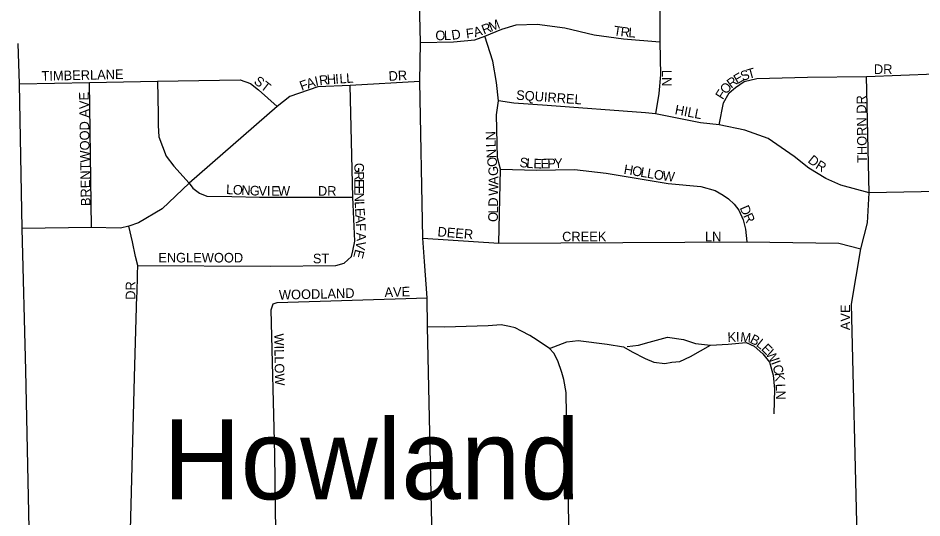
# Model space of a CAD drawing. Extents: x -37878.7 to -37844.7, y -19791.4 to -19769.4.
# Drawn here: x -37871.912 to -37871.021, y -19771.451 to -19770.958 of the extents above; entities that cross this region are included whole.
import ezdxf

# ---------------------------------------------------------------- set-up
doc = ezdxf.new("R2010")
doc.units = 0
for name, color, linetype in [('GM_X_State_Route', 7, 'Continuous'), ('GM_X_Township_Subdivision', 7, 'Continuous'), ('GM_X_Township_Subdivision_Text', 7, 'Continuous'), ('GM_X_Unincorporated_Text', 7, 'Continuous')]:
    doc.layers.add(name, color=color, linetype=linetype)

msp = doc.modelspace()

# ---------------------------------------------------------------- linework, layer by layer
at = {"layer": 'GM_X_State_Route'}
for points in [[(-37871.51143, -19771.19794), (-37871.51308, -19771.17482), (-37871.51633, -19771.02024), (-37871.51551, -19770.982), (-37871.51877, -19770.84776), (-37871.52447, -19770.72084), (-37871.52739, -19770.64449), (-37871.53594, -19770.42871), (-37871.53733, -19770.3854)], [(-37871.4997, -19771.60813), (-37871.5, -19771.5981), (-37871.50303, -19771.51628), (-37871.50868, -19771.26212), (-37871.50889, -19771.23369), (-37871.51143, -19771.19794)]]:
    msp.add_lwpolyline(points, dxfattribs=at)
at = {"layer": 'GM_X_Township_Subdivision'}
for points in [[(-37871.44189, -19770.84491), (-37871.44189, -19770.87054), (-37871.44026, -19770.88437), (-37871.437, -19770.89332), (-37871.4309, -19770.90105), (-37871.41951, -19770.90471), (-37871.39958, -19770.90593), (-37871.30399, -19770.90674), (-37871.29219, -19770.91), (-37871.28568, -19770.91651), (-37871.2808, -19770.92586), (-37871.27958, -19770.94335), (-37871.27958, -19770.98118), (-37871.27876, -19771.01373), (-37871.28039, -19771.03204), (-37871.28388, -19771.0523)], [(-37871.51551, -19770.982), (-37871.48297, -19770.98118), (-37871.46182, -19770.97915), (-37871.45206, -19770.97549), (-37871.43537, -19770.96858), (-37871.42114, -19770.96451), (-37871.40039, -19770.96369), (-37871.37314, -19770.96736), (-37871.34426, -19770.97427), (-37871.31538, -19770.97834), (-37871.27958, -19770.98118)], [(-37871.43837, -19771.17988), (-37871.4366, -19771.10689), (-37871.43944, -19771.0955), (-37871.44066, -19771.05319), (-37871.43863, -19771.03936), (-37871.44066, -19771.02146), (-37871.44433, -19771.0003), (-37871.45206, -19770.97549)], [(-37871.89901, -19771.58554), (-37871.9049, -19771.30525), (-37871.90853, -19771.16537), (-37871.91106, -19771.02247), (-37871.91243, -19770.98276)], [(-37871.91106, -19771.02247), (-37871.84213, -19771.02133), (-37871.77504, -19771.01996), (-37871.69343, -19771.01868), (-37871.68329, -19771.02224), (-37871.6753, -19771.0284), (-37871.65704, -19771.04507)], [(-37871.51633, -19771.02024), (-37871.58495, -19771.0241), (-37871.6167, -19771.02542), (-37871.6443, -19771.03527), (-37871.65704, -19771.04507), (-37871.74354, -19771.12061), (-37871.77024, -19771.14572), (-37871.79352, -19771.15963), (-37871.80311, -19771.16306), (-37871.81156, -19771.16488), (-37871.84008, -19771.16442), (-37871.90853, -19771.16537)], [(-37871.84008, -19771.16442), (-37871.84213, -19771.02133)], [(-37871.77504, -19771.01996), (-37871.77435, -19771.0526), (-37871.77435, -19771.06355), (-37871.77363, -19771.07484), (-37871.76633, -19771.09387), (-37871.75883, -19771.10395), (-37871.74354, -19771.12061), (-37871.74012, -19771.1254), (-37871.73335, -19771.13036), (-37871.72619, -19771.13339), (-37871.70155, -19771.13362), (-37871.67416, -19771.13453), (-37871.58213, -19771.13433)], [(-37871.22098, -19771.06307), (-37871.21662, -19771.04124), (-37871.21108, -19771.03163), (-37871.20496, -19771.02609), (-37871.19623, -19771.02027), (-37871.18371, -19771.01735), (-37871.1339, -19771.01619), (-37871.07566, -19771.01532), (-37871.00785, -19771.01292)], [(-37871.09051, -19771.23985), (-37871.0812, -19771.18538), (-37871.07479, -19771.15976), (-37871.07304, -19771.13006), (-37871.07566, -19771.01532)], [(-37871.59072, -19771.19961), (-37871.58704, -19771.19624), (-37871.58369, -19771.19288), (-37871.58213, -19771.18721), (-37871.58033, -19771.17767), (-37871.58213, -19771.13433), (-37871.58495, -19771.0241)], [(-37871.00468, -19771.1289), (-37871.07304, -19771.13006), (-37871.101, -19771.12248), (-37871.11585, -19771.11608), (-37871.13245, -19771.10589), (-37871.14701, -19771.09424), (-37871.17264, -19771.07647), (-37871.19564, -19771.06832), (-37871.22098, -19771.06307), (-37871.23933, -19771.06104), (-37871.28388, -19771.0523), (-37871.29365, -19771.05137), (-37871.39055, -19771.04397), (-37871.4236, -19771.04177), (-37871.43863, -19771.03936)], [(-37871.4366, -19771.10689), (-37871.40109, -19771.10771), (-37871.36367, -19771.10705), (-37871.33251, -19771.11055), (-37871.27136, -19771.12074), (-37871.23918, -19771.12394), (-37871.22477, -19771.12773), (-37871.2169, -19771.13239), (-37871.21166, -19771.13617), (-37871.20613, -19771.14142), (-37871.20147, -19771.14724), (-37871.19739, -19771.15685), (-37871.19506, -19771.16587), (-37871.19361, -19771.17857)], [(-37871.79517, -19771.23148), (-37871.79512, -19771.22993), (-37871.79467, -19771.2103), (-37871.79444, -19771.20163), (-37871.79649, -19771.19273), (-37871.79946, -19771.17835), (-37871.80311, -19771.16306)], [(-37871.51308, -19771.17482), (-37871.43837, -19771.17988), (-37871.19361, -19771.17857), (-37871.10304, -19771.17985), (-37871.0812, -19771.18538)], [(-37871.79444, -19771.20163), (-37871.66389, -19771.20232), (-37871.59916, -19771.20191), (-37871.59072, -19771.19961)], [(-37871.80471, -19771.58825), (-37871.79763, -19771.31186), (-37871.79517, -19771.23148)], [(-37871.66071, -19771.2397), (-37871.65704, -19771.23814), (-37871.50889, -19771.23369)], [(-37871.65771, -19771.51587), (-37871.6591, -19771.38809), (-37871.66274, -19771.24545), (-37871.66071, -19771.2397)], [(-37871.09516, -19771.60885), (-37871.08339, -19771.53105), (-37871.08487, -19771.46857), (-37871.09051, -19771.23985)], [(-37871.37154, -19771.34903), (-37871.37188, -19771.32697), (-37871.37432, -19771.3143), (-37871.37603, -19771.30723), (-37871.38018, -19771.29576), (-37871.38407, -19771.28821), (-37871.38822, -19771.28357), (-37871.40042, -19771.27528), (-37871.40773, -19771.2709), (-37871.41602, -19771.2665), (-37871.42211, -19771.26333), (-37871.42772, -19771.26187), (-37871.43601, -19771.26041), (-37871.44894, -19771.26114), (-37871.47064, -19771.26187), (-37871.49161, -19771.2626), (-37871.50868, -19771.26212)], [(-37871.38822, -19771.28357), (-37871.37125, -19771.27712), (-37871.36018, -19771.27566), (-37871.33135, -19771.27945), (-37871.31533, -19771.28207), (-37871.30689, -19771.28673), (-37871.29407, -19771.29343), (-37871.28534, -19771.29692), (-37871.27456, -19771.29838), (-37871.26757, -19771.29692), (-37871.25989, -19771.29637), (-37871.24915, -19771.2916), (-37871.22953, -19771.28039), (-37871.21207, -19771.27925), (-37871.19448, -19771.2777), (-37871.18632, -19771.2812), (-37871.17788, -19771.28877), (-37871.17147, -19771.29721), (-37871.16769, -19771.31002), (-37871.16652, -19771.32371), (-37871.1671, -19771.34788)], [(-37871.3116, -19771.28158), (-37871.30048, -19771.28032), (-37871.29, -19771.27741), (-37871.27181, -19771.27249), (-37871.25619, -19771.27467), (-37871.24433, -19771.27855), (-37871.22953, -19771.28039)], [(-37871.36254, -19771.7401), (-37871.36549, -19771.60206), (-37871.36813, -19771.50983), (-37871.36993, -19771.41987), (-37871.37042, -19771.39232), (-37871.37042, -19771.38354), (-37871.3714, -19771.37525), (-37871.3714, -19771.36989), (-37871.3714, -19771.35794), (-37871.37154, -19771.34903)]]:
    msp.add_lwpolyline(points, dxfattribs=at)

# ---------------------------------------------------------------- texts
at = {"layer": 'GM_X_Township_Subdivision_Text'}
for s, height, rotation, p in [('M', 0.00947, 21.91655, (-37871.44596, -19770.97133)), ('F', 0.00947, 7.12163, (-37871.47012, -19770.97794)), ('A', 0.00947, 16.84628, (-37871.46179, -19770.97675)), ('R', 0.00947, 21.0736, (-37871.45309, -19770.97409)), ('T', 0.00947, 351.3909, (-37871.32556, -19770.97463)), ('R', 0.00947, 353.5131, (-37871.3186, -19770.97568)), ('L', 0.00947, 355.81811, (-37871.31074, -19770.97656)), ('O', 0.00947, 0.18581, (-37871.50083, -19770.97961)), ('L', 0.00947, 0.93643, (-37871.49237, -19770.97958)), ('D', 0.00947, 8.68988, (-37871.4843, -19770.97935)), ('DR', 0.00947, 0.00001, (-37871.06834, -19771.01294)), ('TIMBERLANE', 0.00947, 1.28784, (-37871.88921, -19771.01961)), ('L', 0.00947, 4.08599, (-37871.5885, -19771.02187)), ('DR', 0.00947, 3.01732, (-37871.54676, -19771.01973)), ('LN', 0.00947, 270, (-37871.2774, -19771.00889)), ('E', 0.00947, 30.282, (-37871.20328, -19771.02322)), ('S', 0.00947, 20.32266, (-37871.19791, -19771.02005)), ('T', 0.00947, 15.82532, (-37871.19185, -19771.01779)), ('ST', 0.00947, 322.43061, (-37871.68063, -19771.02161)), ('F', 0.00947, 20.22752, (-37871.63266, -19771.02967)), ('A', 0.00947, 17.53727, (-37871.62651, -19771.0274)), ('I', 0.00947, 12.15675, (-37871.61879, -19771.02495)), ('R', 0.00947, 6.77624, (-37871.61495, -19771.02411)), ('H', 0.00947, 4.08599, (-37871.60762, -19771.02324)), ('I', 0.00947, 4.08599, (-37871.59931, -19771.02264)), ('L', 0.00947, 4.08599, (-37871.59515, -19771.02235)), ('R', 0.00947, 36.55415, (-37871.20907, -19771.02754)), ('SQUIRREL', 0.00947, 355.7938, (-37871.42144, -19771.0382)), ('F', 0.00947, 57.68179, (-37871.2174, -19771.03885)), ('O', 0.00947, 49.71872, (-37871.21404, -19771.0335)), ('BRENTWOOD AVE', 0.0094697, 90.94644, (-37871.84095, -19771.14308)), ('THORN DR', 0.00947, 90.80648, (-37871.07513, -19771.10058)), ('HILL', 0.00947, 349.04572, (-37871.26524, -19771.05245)), ('N', 0.00947, 91.6394, (-37871.44145, -19771.07828)), ('L', 0.00947, 91.63906, (-37871.44126, -19771.08494)), ('N', 0.00947, 93.08345, (-37871.44074, -19771.0957)), ('D', 0.00947, 320.72059, (-37871.13425, -19771.09932)), ('G', 0.00947, 270.02187, (-37871.58073, -19771.10055)), ('O', 0.00947, 99.90637, (-37871.43934, -19771.10362)), ('S', 0.00947, 354.67818, (-37871.41817, -19771.10461)), ('L', 0.00947, 354.67818, (-37871.41153, -19771.10523)), ('E', 0.00947, 357.9581, (-37871.4043, -19771.10589)), ('E', 0.00947, 1.61998, (-37871.39697, -19771.10613)), ('P', 0.00947, 1.78311, (-37871.39028, -19771.10594)), ('Y', 0.00947, 1.79058, (-37871.38362, -19771.10573)), ('R', 0.00947, 328.16818, (-37871.12673, -19771.10536)), ('R', 0.00947, 270.03548, (-37871.58072, -19771.10889)), ('G', 0.00947, 92.91916, (-37871.43877, -19771.11319)), ('H', 0.00947, 350.40474, (-37871.31554, -19771.1113)), ('O', 0.00947, 350.39397, (-37871.30732, -19771.11269)), ('L', 0.00947, 350.41119, (-37871.29911, -19771.11408)), ('L', 0.00947, 350.39397, (-37871.29253, -19771.11519)), ('O', 0.00947, 350.41044, (-37871.28596, -19771.1163)), ('W', 0.00947, 353.34489, (-37871.27722, -19771.11776)), ('E', 0.00947, 270.02733, (-37871.58072, -19771.11639)), ('A', 0.00947, 89.32248, (-37871.43886, -19771.12217)), ('L', 0.00947, 357.15806, (-37871.70742, -19771.13127)), ('O', 0.00947, 357.16115, (-37871.70076, -19771.1316)), ('N', 0.00947, 357.15563, (-37871.69243, -19771.13202)), ('G', 0.00947, 357.35823, (-37871.68408, -19771.13243)), ('V', 0.00947, 359.23274, (-37871.67541, -19771.13282)), ('I', 0.00947, 359.96207, (-37871.66695, -19771.13294)), ('E', 0.00947, 359.99563, (-37871.66277, -19771.13294)), ('W', 0.00947, 359.99878, (-37871.65611, -19771.13294)), ('DR', 0.00947, 0.00001, (-37871.61667, -19771.13294)), ('E', 0.00947, 270.02733, (-37871.58071, -19771.12306)), ('W', 0.00947, 89.32181, (-37871.43899, -19771.133)), ('N', 0.00947, 271.41838, (-37871.58071, -19771.12997)), ('D', 0.00947, 89.32851, (-37871.43911, -19771.14384)), ('L', 0.00947, 273.17326, (-37871.58049, -19771.13862)), ('E', 0.00947, 273.19187, (-37871.58012, -19771.14528)), ('L', 0.00947, 89.31696, (-37871.43919, -19771.15051)), ('D', 0.00947, 293.37655, (-37871.20087, -19771.14486)), ('A', 0.00947, 273.19257, (-37871.57975, -19771.15194)), ('O', 0.00947, 89.32248, (-37871.43929, -19771.15885)), ('R', 0.00947, 294.54134, (-37871.19748, -19771.1527)), ('F', 0.00947, 273.17967, (-37871.57928, -19771.16025)), ('DEER', 0.00947, 355.23887, (-37871.49902, -19771.17295)), ('A', 0.00947, 271.53016, (-37871.57878, -19771.16934)), ('CREEK', 0.00947, 0.00001, (-37871.37584, -19771.17794)), ('LN', 0.00947, 0.00001, (-37871.23501, -19771.17794)), ('V', 0.00947, 260.97965, (-37871.57852, -19771.17721)), ('ENGLEWOOD', 0.00947, 0.00001, (-37871.77417, -19771.19877)), ('ST', 0.00947, 0.00001, (-37871.62167, -19771.1996)), ('E', 0.00947, 255.75836, (-37871.57978, -19771.18522)), ('DR', 0.00947, 90, (-37871.79678, -19771.23555)), ('WOODLAND', 0.00947, 1.3964, (-37871.65505, -19771.23544)), ('AVE', 0.00947, 1.97389, (-37871.5509, -19771.23294)), ('AVE', 0.00947, 90, (-37871.0918, -19771.26555)), ('WILLOW', 0.00947, 270.98722, (-37871.65989, -19771.26886)), ('K', 0.00947, 1.48616, (-37871.21264, -19771.27711)), ('I', 0.00947, 1.48177, (-37871.20431, -19771.27689)), ('M', 0.00947, 354.20786, (-37871.20046, -19771.27677)), ('B', 0.00947, 333.45667, (-37871.19138, -19771.27753)), ('L', 0.00947, 321.75837, (-37871.1851, -19771.28061)), ('E', 0.00947, 315.6279, (-37871.18006, -19771.28456)), ('W', 0.00947, 303.04185, (-37871.17564, -19771.2888)), ('I', 0.00947, 290.68137, (-37871.16998, -19771.2974)), ('C', 0.00947, 287.02953, (-37871.16856, -19771.30114)), ('K', 0.00947, 277.56287, (-37871.16645, -19771.30791)), ('L', 0.00947, 272.45989, (-37871.16523, -19771.31845)), ('N', 0.00947, 270.37156, (-37871.16495, -19771.32501))]:
    msp.add_text(s, height=height, rotation=rotation, dxfattribs=at).set_placement(p)
at = {"layer": 'GM_X_Unincorporated_Text'}
msp.add_text('Howland', height=0.078977, rotation=0.00001, dxfattribs=at).set_placement((-37871.76917, -19771.43226))

doc.saveas('drawing.dxf')
